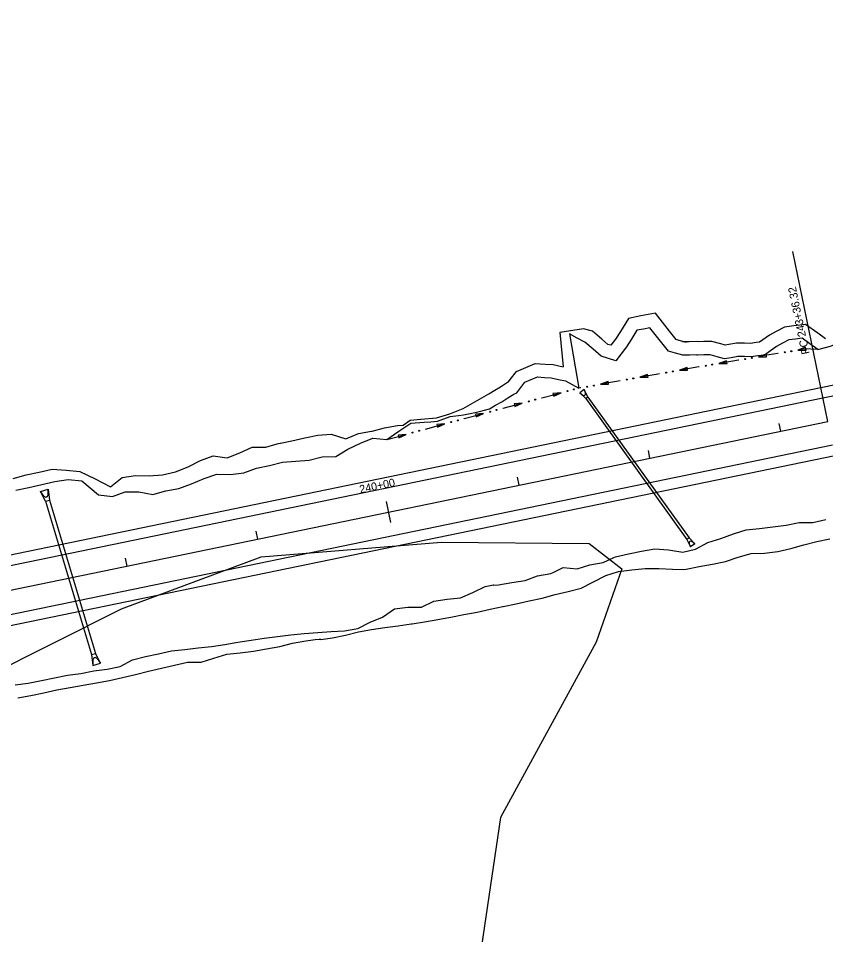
# Model space of a CAD drawing. Extents: x 979959 to 994833, y 1835619 to 1845316.
# Drawn here: x 989427 to 990032, y 1838507 to 1839194 of the extents above; entities that cross this region are included whole.
import ezdxf

# ---------------------------------------------------------------- set-up
doc = ezdxf.new("R2010")
doc.units = 0
for name, color, linetype in [('43', 7, 'Continuous'), ('Future 5 Lane Construction Limits', 7, 'Continuous'), ('R_Drainage', 7, 'Continuous'), ('R_Horz Alg', 7, 'Continuous'), ('R_Horz Alg Annot', 7, 'Continuous'), ('R_Horz Alg Stationing', 7, 'Continuous'), ('R_Proposed Const Limits', 7, 'Continuous'), ('R_Proposed Road', 7, 'Continuous'), ('R_Special Ditch', 7, 'Continuous')]:
    doc.layers.add(name, color=color, linetype=linetype)

msp = doc.modelspace()

# ---------------------------------------------------------------- linework, layer by layer
at = {"layer": '43'}
msp.add_lwpolyline([(989403, 1838700.1), (989504.63, 1838750.9), (989609.33, 1838790.02), (989744.49, 1838800.99), (989854.96, 1838799.84), (989879.42, 1838780.86), (989860.38, 1838726.09), (989788.47, 1838594.56), (989762.26, 1838416.86)], dxfattribs=at)
at = {"layer": 'Future 5 Lane Construction Limits'}
msp.add_line((989720.97, 1838892.48), (989728.82, 1838893.17), dxfattribs=at)
for points in [[(989928, 1838950.67), (989922.57, 1838952.23), (989920.23, 1838952.9), (989915.31, 1838959.15), (989904.6, 1838972.73), (989893.69, 1838970.56), (989884.51, 1838968.74), (989878.4, 1838958.83), (989874.85, 1838953.08), (989871.35, 1838948.55), (989869.02, 1838949.27), (989864.39, 1838953.2), (989857.41, 1838959.12), (989850.75, 1838960.83), (989832.97, 1838958.08), (989835.58, 1838932.42)], [(990032.16, 1838953.49), (990026.23, 1838957.72), (990017.12, 1838964.22), (990008.26, 1838963.09), (990001.44, 1838962.22), (989995.22, 1838958.88), (989990.07, 1838956.11), (989985.11, 1838952.59), (989982.71, 1838950.88), (989980.23, 1838950.57), (989975.89, 1838950.02), (989971.42, 1838950.03), (989965.5, 1838950.05), (989959.75, 1838949.12), (989956.92, 1838948.67), (989953.59, 1838949.56), (989946.82, 1838951.38), (989940.81, 1838951.28), (989936.91, 1838951.21), (989935.88, 1838951.34), (989930.05, 1838951.19), (989924.97, 1838951.05)], [(989760.54, 1838901.08), (989779.91, 1838912.25), (989784.31, 1838914.79), (989788.67, 1838917.53), (989793.92, 1838920.83), (989794.51, 1838921.07), (989795.88, 1838922.88), (989800.51, 1838928.99), (989807.64, 1838932.03), (989814.55, 1838934.98), (989822.14, 1838934.45), (989828.02, 1838934.04), (989835.58, 1838932.42)], [(989728.82, 1838893.17), (989740.5, 1838894.17), (989750.5, 1838897.15), (989760.54, 1838901.08)], [(989672.68, 1838878.41), (989682.09, 1838882.31), (989691.91, 1838884.18), (989692.45, 1838884.28), (989701.59, 1838886.76), (989711.45, 1838888.47), (989715.66, 1838888.61), (989720.97, 1838892.48)], [(989496.32, 1838842.39), (989505.08, 1838849.41), (989514.99, 1838850.88), (989525.23, 1838850.75), (989535.3, 1838851.41), (989545.04, 1838853.7), (989554.48, 1838857.44), (989563.69, 1838862.3), (989573.19, 1838865.74), (989583.74, 1838864.11), (989593.17, 1838867.85), (989602.5, 1838872.12), (989612.71, 1838872.14), (989619.47, 1838874.14), (989622.33, 1838874.99), (989623.61, 1838875.28), (989623.62, 1838875.29), (989632.12, 1838877.04), (989641.91, 1838879.06), (989651.68, 1838881.22), (989661.73, 1838882), (989672.68, 1838878.41)], [(989423.54, 1838848.7), (989433.2, 1838851.37), (989442.97, 1838853.53), (989452.72, 1838855.74), (989463.08, 1838855.03), (989473.49, 1838854.05), (989484.86, 1838848.45), (989496.32, 1838842.39)], [(989426.87, 1838684.2), (989436.71, 1838686.01), (989446.5, 1838688.05), (989456.27, 1838690.18), (989466.11, 1838691.96), (989475.97, 1838693.64), (989485.82, 1838695.39), (989495.67, 1838697.15), (989505.42, 1838699.41), (989515.17, 1838701.64), (989524.86, 1838704.15), (989534.6, 1838706.45), (989544.35, 1838708.65), (989554.1, 1838710.9), (989564.3, 1838710.94), (989573.87, 1838714.04), (989583.48, 1838716.98), (989593.5, 1838717.9), (989603.45, 1838719.14), (989613.29, 1838720.97), (989623.14, 1838722.71), (989632.84, 1838725.16), (989642.66, 1838727.07), (989649.65, 1838727.93), (989652.63, 1838728.2), (989653.95, 1838728.31), (989654.04, 1838727.92), (989662.65, 1838729.18), (989672.41, 1838731.35), (989682.14, 1838733.65), (989691.97, 1838735.52), (989701.87, 1838737.01), (989711.84, 1838738.16), (989721.73, 1838739.75), (989722.27, 1838739.82), (989731.64, 1838741.2), (989741.5, 1838742.9), (989745.59, 1838743.62), (989751.35, 1838744.64), (989761.13, 1838746.74), (989770.98, 1838748.46), (989780.71, 1838750.82), (989790.31, 1838752.67), (989790.53, 1838752.69), (989800.31, 1838754.8), (989810.08, 1838756.9), (989819.87, 1838758.98), (989829.53, 1838761.62), (989839.25, 1838764), (989848.96, 1838766.42), (989858.2, 1838771.12), (989867.41, 1838775.99), (989876.99, 1838779.03), (989886.97, 1838780.18), (989896.98, 1838781.14), (989907.17, 1838781.24), (989917.49, 1838780.73), (989925.97, 1838780.38), (989927.7, 1838780.72), (989937.51, 1838782.64), (989947.33, 1838784.56), (989957.14, 1838786.49), (989966.69, 1838789.71), (989976.34, 1838792.42), (989986.49, 1838792.68), (989996.45, 1838793.91), (990006.17, 1838796.29), (990015.81, 1838799.08), (990025.5, 1838801.56), (990035.3, 1838803.57)]]:
    msp.add_lwpolyline(points, dxfattribs=at)
at = {"layer": 'R_Drainage'}
for p, q in [((989851.29, 1838915.29), (989848.04, 1838912.95)), ((989854.04, 1838909.73), (989851.29, 1838915.29)), ((989851.29, 1838915.29), (989852.2, 1838912.49)), ((989852.42, 1838908.57), (989848.04, 1838912.95)), ((989848.04, 1838912.95), (989850.39, 1838911.2)), ((989854.04, 1838909.73), (989852.42, 1838908.57)), ((989852.42, 1838908.57), (989928.21, 1838802.95)), ((989854.04, 1838909.73), (989929.84, 1838804.11)), ((989443.97, 1838839.03), (989449.72, 1838840.75)), ((989447.75, 1838831.65), (989443.97, 1838839.03)), ((989446.53, 1838835.48), (989443.97, 1838839.03)), ((989449.54, 1838836.39), (989449.72, 1838840.75)), ((989449.72, 1838840.75), (989450.62, 1838832.51)), ((989447.75, 1838831.65), (989450.62, 1838832.51)), ((989447.75, 1838831.65), (989482.16, 1838716.69)), ((989450.62, 1838832.51), (989485.03, 1838717.55)), ((989929.84, 1838804.11), (989928.21, 1838802.95)), ((989929.84, 1838804.11), (989934.22, 1838799.72)), ((989928.21, 1838802.95), (989930.97, 1838797.39)), ((989930.97, 1838797.39), (989930.06, 1838800.19)), ((989934.22, 1838799.72), (989930.97, 1838797.39)), ((989934.22, 1838799.72), (989931.86, 1838801.48)), ((989482.16, 1838716.69), (989485.03, 1838717.55)), ((989482.16, 1838716.69), (989483.06, 1838708.45)), ((989488.81, 1838710.18), (989485.03, 1838717.55)), ((989483.24, 1838712.82), (989483.06, 1838708.45)), ((989483.06, 1838708.45), (989488.81, 1838710.18)), ((989486.26, 1838713.72), (989488.81, 1838710.18))]:
    msp.add_line(p, q, dxfattribs=at)
for centre, radius, start, end in [((989851.09, 1838912.13), 1.17, 233.1943, 18.13446), ((989447.88, 1838836.45), 1.67, 215.707, 357.62176), ((989931.16, 1838800.55), 1.17, 53.1943, 198.13445), ((989484.91, 1838712.75), 1.67, 35.707, 177.62176)]:
    msp.add_arc(centre, radius, start, end, dxfattribs=at)
at = {"layer": 'R_Horz Alg'}
msp.add_line((984572.47, 1837764.03), (990033.82, 1838891.48), dxfattribs=at)
at = {"layer": 'R_Horz Alg Annot'}
msp.add_lwpolyline([(990033.82, 1838891.48), (990007.54, 1839018.8)], dxfattribs=at)
at = {"layer": 'R_Horz Alg Stationing'}
for points in [[(989997.03, 1838890.01), (989998.25, 1838884.14)], [(989899.1, 1838869.79), (989900.31, 1838863.92)], [(989801.16, 1838849.58), (989802.38, 1838843.7)], [(989702.82, 1838831.32), (989706.06, 1838815.65)], [(989605.29, 1838809.14), (989606.51, 1838803.27)], [(989507.36, 1838788.92), (989508.57, 1838783.05)]]:
    msp.add_lwpolyline(points, dxfattribs=at)
at = {"layer": 'R_Proposed Const Limits'}
for points in [[(989925.23, 1838941.06), (989919.8, 1838942.62), (989914.37, 1838944.18), (989907.46, 1838952.96), (989900.54, 1838961.73), (989895.64, 1838960.76), (989890.73, 1838959.78), (989886.91, 1838953.58), (989883.08, 1838947.38), (989879.05, 1838942.16), (989875.02, 1838936.95), (989869.57, 1838938.64), (989864.12, 1838940.32), (989857.93, 1838945.57), (989851.74, 1838950.82), (989845.99, 1838953.93), (989840.24, 1838957.04), (989847.22, 1838916.45)], [(990026.35, 1838945.35), (990035.76, 1838947.81), (990044.87, 1838951.59), (990051.99, 1838954.66)], [(990026.35, 1838945.35), (990020.42, 1838949.58), (990014.5, 1838953.81), (990009.52, 1838953.17), (990004.55, 1838952.54), (989999.95, 1838950.07), (989995.36, 1838947.6), (989990.9, 1838944.43), (989986.45, 1838941.27), (989981.47, 1838940.65), (989976.5, 1838940.02), (989971.39, 1838940.03), (989966.28, 1838940.05), (989961.34, 1838939.25), (989956.4, 1838938.46), (989951, 1838939.91), (989945.59, 1838941.36), (989940.98, 1838941.28), (989936.37, 1838941.2), (989935.88, 1838941.26), (989935.39, 1838941.32), (989930.31, 1838941.19), (989925.23, 1838941.06)], [(989780.35, 1838900.96), (989784.91, 1838903.59), (989789.47, 1838906.22), (989793.99, 1838909.06), (989798.51, 1838911.9), (989800.83, 1838912.85), (989803.85, 1838916.84), (989806.87, 1838920.83), (989811.57, 1838922.83), (989816.26, 1838924.84), (989821.44, 1838924.47), (989826.62, 1838924.11), (989831.96, 1838922.97), (989837.3, 1838921.83), (989842.26, 1838919.14), (989847.22, 1838916.45)], [(989703.44, 1838877.81), (989712.32, 1838884.25), (989721.28, 1838890.28), (989731.38, 1838890.85), (989736.4, 1838891.26), (989741.42, 1838891.67), (989750.9, 1838895.18), (989757.2, 1838895.88), (989760.87, 1838896.39), (989765.77, 1838897.36), (989770.67, 1838898.34), (989775.51, 1838899.65), (989780.35, 1838900.96)], [(989665.21, 1838865.14), (989674.27, 1838870.73), (989683.56, 1838875.19), (989692.98, 1838879.02), (989703.44, 1838877.81)], [(989497.82, 1838835.14), (989507.32, 1838838.57), (989517.5, 1838838.73), (989528.14, 1838836.64), (989537.78, 1838839.39), (989547.6, 1838841.29), (989557.12, 1838844.66), (989566.51, 1838848.63), (989576.05, 1838851.87), (989586.29, 1838851.74), (989596.26, 1838852.91), (989605.72, 1838856.53), (989615.52, 1838858.51), (989625.21, 1838861.05), (989635.31, 1838861.6), (989645.33, 1838862.52), (989655.06, 1838864.84), (989665.21, 1838865.14)], [(989425.37, 1838839.84), (989435.13, 1838842.01), (989444.88, 1838844.26), (989454.63, 1838846.48), (989464.55, 1838847.93), (989474.96, 1838846.92), (989487.33, 1838836.48), (989497.82, 1838835.14)], [(989424.86, 1838693.92), (989434.78, 1838695.36), (989444.6, 1838697.24), (989454.38, 1838699.32), (989464.17, 1838701.34), (989474.14, 1838702.54), (989483.94, 1838704.51), (989493.9, 1838705.72), (989503.69, 1838707.79), (989512.85, 1838712.85), (989522.57, 1838715.26), (989532.38, 1838717.16), (989542.12, 1838719.44), (989552.15, 1838720.36), (989562.09, 1838721.65), (989572.08, 1838722.7), (989582, 1838724.13), (989591.85, 1838725.87), (989601.75, 1838727.37), (989611.62, 1838729.02), (989621.57, 1838730.32), (989631.52, 1838731.56), (989641.54, 1838732.51), (989651.61, 1838733.17), (989661.67, 1838733.9), (989671.74, 1838734.56), (989681.63, 1838736.13), (989690.85, 1838740.95), (989700.25, 1838744.85), (989709.22, 1838750.87), (989719.16, 1838752.2), (989729.34, 1838752.34), (989738.63, 1838756.79), (989748.53, 1838758.29), (989758.58, 1838759.1), (989767.91, 1838763.33), (989777.21, 1838767.75), (989783.39, 1838769.02), (989783.47, 1838768.71), (989787.19, 1838768.87), (989797.03, 1838770.68), (989806.95, 1838772.11), (989816.4, 1838775.78), (989826.24, 1838777.57), (989828.57, 1838778.49), (989835.55, 1838781.94), (989845.95, 1838781.01), (989855.54, 1838784.03), (989865.4, 1838785.73), (989873.42, 1838789.58), (989874.72, 1838790.02), (989884.49, 1838792.16), (989894.27, 1838794.24), (989904.12, 1838796.03), (989914.49, 1838795.22), (989925.09, 1838793.37), (989934.8, 1838795.76), (989944.02, 1838800.58), (989953.59, 1838803.67), (989963.07, 1838807.23), (989963.98, 1838807.45), (989972.68, 1838810.16), (989982.66, 1838811.25), (989992.63, 1838812.4), (990002.57, 1838813.72), (990012.38, 1838815.68), (990022.57, 1838815.75), (990032.31, 1838818.04)]]:
    msp.add_lwpolyline(points, dxfattribs=at)
at = {"layer": 'R_Proposed Road'}
for p, q in [((984567.22, 1837789.49), (990028.56, 1838916.94)), ((984568.84, 1837781.66), (990030.18, 1838909.11)), ((984576.11, 1837746.4), (990037.46, 1838873.85)), ((984577.73, 1837738.57), (990039.08, 1838866.02))]:
    msp.add_line(p, q, dxfattribs=at)
for radius in [1883.86, 1891.86]:
    msp.add_arc((989647.69, 1840761.9), radius, 281.66438, 303.64915, dxfattribs=at)
at = {"layer": 'R_Special Ditch'}
for p, q in [((989987.55, 1838942.02), (989981.81, 1838939.97)), ((989987.91, 1838939.94), (989987.55, 1838942.02)), ((990017.16, 1838947.07), (990011.43, 1838945.02)), ((990011.43, 1838945.02), (990017.52, 1838944.99)), ((990017.52, 1838944.99), (990017.16, 1838947.07)), ((989957.94, 1838936.98), (989952.2, 1838934.93)), ((989952.2, 1838934.93), (989958.3, 1838934.89)), ((989958.3, 1838934.89), (989957.94, 1838936.98)), ((989981.81, 1838939.97), (989987.91, 1838939.94)), ((989928.33, 1838931.89), (989922.61, 1838929.81)), ((989922.61, 1838929.81), (989928.7, 1838929.8)), ((989928.7, 1838929.8), (989928.33, 1838931.89)), ((989869.17, 1838921.41), (989863.45, 1838919.31)), ((989869.55, 1838919.33), (989869.17, 1838921.41)), ((989898.75, 1838926.68), (989893.02, 1838924.59)), ((989893.02, 1838924.59), (989899.12, 1838924.59)), ((989899.12, 1838924.59), (989898.75, 1838926.68)), ((989863.45, 1838919.31), (989869.55, 1838919.33)), ((989833.96, 1838912.89), (989827.89, 1838912.38)), ((989827.89, 1838912.38), (989828.43, 1838910.33)), ((989828.43, 1838910.33), (989833.96, 1838912.89)), ((989804.92, 1838905.19), (989798.85, 1838904.67)), ((989798.85, 1838904.67), (989799.4, 1838902.63)), ((989799.4, 1838902.63), (989804.92, 1838905.19)), ((989775.9, 1838897.44), (989769.83, 1838896.91)), ((989769.83, 1838896.91), (989770.38, 1838894.87)), ((989770.38, 1838894.87), (989775.9, 1838897.44)), ((989746.9, 1838889.63), (989740.83, 1838889.09)), ((989740.83, 1838889.09), (989741.38, 1838887.05)), ((989741.38, 1838887.05), (989746.9, 1838889.63)), ((989717.91, 1838881.77), (989711.84, 1838881.21)), ((989711.84, 1838881.21), (989712.4, 1838879.17)), ((989712.4, 1838879.17), (989717.91, 1838881.77))]:
    msp.add_line(p, q, dxfattribs=at)
for points in [[(989996.6, 1838942.49), (989996.42, 1838942.46), (989986.55, 1838940.78), (989981.81, 1838939.97)], [(989996.64, 1838942.5), (989996.6, 1838942.49)], [(990026.35, 1838945.35), (990016.14, 1838945.82), (990011.43, 1838945.02)], [(989966.99, 1838937.45), (989966.82, 1838937.42), (989956.96, 1838935.74), (989952.2, 1838934.93)], [(989967.03, 1838937.45), (989966.99, 1838937.45)], [(989907.79, 1838927.2), (989907.67, 1838927.18), (989905.19, 1838926.74), (989897.82, 1838925.44), (989893.02, 1838924.59)], [(989907.83, 1838927.21), (989907.8, 1838927.2)], [(989937.38, 1838932.4), (989937.23, 1838932.37), (989927.38, 1838930.65), (989922.61, 1838929.81)], [(989937.42, 1838932.4), (989937.38, 1838932.4)], [(989878.22, 1838921.95), (989878.12, 1838921.94), (989868.28, 1838920.17), (989863.45, 1838919.31)], [(989878.26, 1838921.96), (989878.22, 1838921.95)], [(989848.65, 1838916.64), (989848.59, 1838916.63), (989847.24, 1838916.39)], [(989848.69, 1838916.65), (989848.65, 1838916.64)], [(989819.42, 1838909.04), (989819.46, 1838909.05)], [(989819.46, 1838909.05), (989819.51, 1838909.07), (989829.2, 1838911.63), (989833.96, 1838912.89)], [(989790.39, 1838901.32), (989790.43, 1838901.33)], [(989790.43, 1838901.33), (989790.48, 1838901.34), (989800.15, 1838903.93), (989802.55, 1838904.56), (989804.92, 1838905.19)], [(989761.38, 1838893.54), (989761.41, 1838893.55)], [(989761.41, 1838893.55), (989761.45, 1838893.56), (989771.12, 1838896.16), (989775.9, 1838897.44)], [(989732.42, 1838885.71), (989732.44, 1838885.72), (989742.11, 1838888.34), (989746.9, 1838889.63)], [(989703.44, 1838877.81), (989713.1, 1838880.46), (989717.91, 1838881.77)], [(989732.38, 1838885.7), (989732.42, 1838885.71)]]:
    msp.add_lwpolyline(points, dxfattribs=at)
for centre in [(990001.56, 1838943.3), (990006.5, 1838944.14), (989947.28, 1838934.05), (989971.95, 1838938.25), (989976.89, 1838939.1), (989912.75, 1838928.04), (989917.68, 1838928.91), (989942.34, 1838933.21), (989883.17, 1838922.8), (989888.1, 1838923.68), (989838.79, 1838914.2), (989843.63, 1838915.48), (989853.6, 1838917.5), (989858.53, 1838918.39), (989809.75, 1838906.52), (989814.59, 1838907.8), (989785.57, 1838900.07), (989756.56, 1838892.28), (989780.73, 1838898.77), (989751.72, 1838890.97), (989722.73, 1838883.12), (989727.56, 1838884.43)]:
    msp.add_circle(centre, 0.375, dxfattribs=at)

# ---------------------------------------------------------------- texts
at = {"layer": 'R_Horz Alg Annot'}
msp.add_text('PC 243+36.32', height=6, rotation=101.66438, dxfattribs=at).set_placement((990020.24, 1838942.42))
at = {"layer": 'R_Horz Alg Stationing'}
msp.add_text('240+00', height=6, rotation=11.66438, dxfattribs=at).set_placement((989683.52, 1838837.54))

doc.saveas('drawing.dxf')
